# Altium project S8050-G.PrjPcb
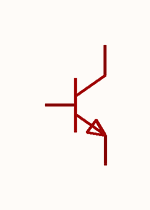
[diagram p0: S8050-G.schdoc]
1 sheet, 1 parts. Net scope: global (net labels, ports and power ports of the same name join across sheets).

## Sheet S8050-G.schdoc
size 127 x 101 mm

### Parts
Q?  s8050-g(range:200-350)  [SOT-23-3_L2.9-W1.3-P1.90-LS2.4-BR]  (value not drawn)

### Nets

Not connected (* = marked no-connect by the designer): Q? 1(B) 2(E) 3(C)

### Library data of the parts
Q? = s8050-g(range:200-350): 晶体管类型:NPN;集电极电流(Ic):500mA;集射极击穿电压(Vceo):25V;耗散功率(Pd):300mW;直流电流增益(hFE):200;; Manufacturer: CJ(江苏长电/长晶); AddInBom: yes; ModelId: c62791f0466c4ae2a892c056b845b0ca; ModelName: SOT-23-3P_L2.9-W1.3-H1.0-LS2.4-P0.95; ModelTransform: 98.425,114.173,0,180,0,0,0.0005,-0.0005,0; type: NPN; Current - Collector(Ic): 500mA; Collector - Emitter Voltage VCEO: 25V; Pd - Power Dissipation: 300mW; DC Current Gain: 200; Transition frequency(fT): 150MHz; Current - Collector Cutoff: 100nA; Vce Saturation(VCE(sat)): 600mV; Emitter-Base Voltage(Vebo): 5V; Number: 1个NPN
